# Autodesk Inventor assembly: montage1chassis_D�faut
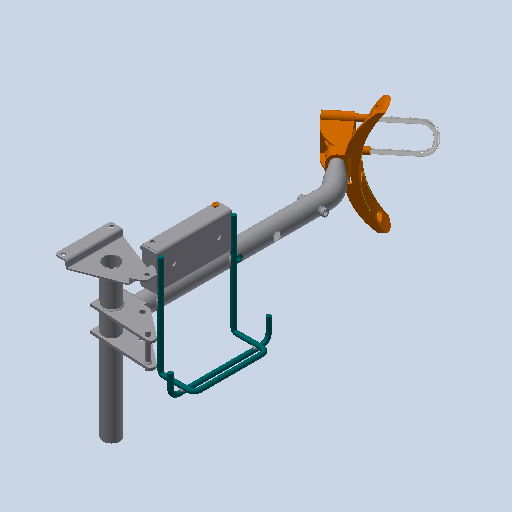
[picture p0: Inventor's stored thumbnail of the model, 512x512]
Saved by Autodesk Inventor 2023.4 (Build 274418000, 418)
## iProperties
Created: 2011-01
Part Number: montage1chassis_D�faut
Document SubType Name: Assembly
Designer: eric
Mass: 436.366 g
Surface Area: 3477.71 cm^2
Volume: 436.366 cm^3
Density: 1 g/cm^3
Author: eric
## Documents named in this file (26)
- C:\Users\bruno\Documents\1-Cours-2024-25\TSsI\7-Dynamique\chariot de golf\chariot_de_golf\chariot_de_golf_trolem\montage1chassis_Defaut.iam
- C:\Users\bruno\Documents\1-Cours-2024-25\TSsI\7-Dynamique\chariot de golf\chariot_de_golf\chariot_de_golf_trolem\bead16_Defaut.ipt
- C:\Users\bruno\Documents\1-Cours-2024-25\TSsI\7-Dynamique\chariot de golf\chariot_de_golf\chariot_de_golf_trolem\1boitier_assemble_Defaut.iam
- C:\Users\bruno\Documents\1-Cours-2024-25\TSsI\7-Dynamique\chariot de golf\chariot_de_golf\chariot_de_golf_trolem\1tube_Defaut.ipt
- C:\Users\bruno\Documents\1-Cours-2024-25\TSsI\7-Dynamique\chariot de golf\chariot_de_golf\chariot_de_golf_trolem\bead7_Defaut.ipt
- C:\Users\bruno\Documents\1-Cours-2024-25\TSsI\7-Dynamique\chariot de golf\chariot_de_golf\chariot_de_golf_trolem\bead3_Defaut.ipt
- C:\Users\bruno\Documents\1-Cours-2024-25\TSsI\7-Dynamique\chariot de golf\chariot_de_golf\chariot_de_golf_trolem\bead15_Defaut.ipt
- C:\Users\bruno\Documents\1-Cours-2024-25\TSsI\7-Dynamique\chariot de golf\chariot_de_golf\chariot_de_golf_trolem\bead4_Defaut.ipt
- C:\Users\bruno\Documents\1-Cours-2024-25\TSsI\7-Dynamique\chariot de golf\chariot_de_golf\chariot_de_golf_trolem\bead18_Defaut.ipt
- C:\Users\bruno\Documents\1-Cours-2024-25\TSsI\7-Dynamique\chariot de golf\chariot_de_golf\chariot_de_golf_trolem\1support_batterie_Defaut.iam
- C:\Users\bruno\Documents\1-Cours-2024-25\TSsI\7-Dynamique\chariot de golf\chariot_de_golf\chariot_de_golf_trolem\1bossage_Defaut.ipt
- C:\Users\bruno\Documents\1-Cours-2024-25\TSsI\7-Dynamique\chariot de golf\chariot_de_golf\chariot_de_golf_trolem\1tube_gauche_Defaut.ipt
- C:\Users\bruno\Documents\1-Cours-2024-25\TSsI\7-Dynamique\chariot de golf\chariot_de_golf\chariot_de_golf_trolem\46Vis CBLZ M5-10.ipt
- C:\Users\bruno\Documents\1-Cours-2024-25\TSsI\7-Dynamique\chariot de golf\chariot_de_golf\chariot_de_golf_trolem\bead8_Defaut.ipt
- C:\Users\bruno\Documents\1-Cours-2024-25\TSsI\7-Dynamique\chariot de golf\chariot_de_golf\chariot_de_golf_trolem\5.1roulement_12x28x8_Defaut.iam
- C:\Users\bruno\Documents\1-Cours-2024-25\TSsI\7-Dynamique\chariot de golf\chariot_de_golf\chariot_de_golf_trolem\41support_bas_Defaut.ipt
- C:\Users\bruno\Documents\1-Cours-2024-25\TSsI\7-Dynamique\chariot de golf\chariot_de_golf\chariot_de_golf_trolem\1bossage2_Defaut.ipt
- C:\Users\bruno\Documents\1-Cours-2024-25\TSsI\7-Dynamique\chariot de golf\chariot_de_golf\chariot_de_golf_trolem\bead14_Defaut.ipt
- C:\Users\bruno\Documents\1-Cours-2024-25\TSsI\7-Dynamique\chariot de golf\chariot_de_golf\chariot_de_golf_trolem\1chape_Defaut.ipt
- C:\Users\bruno\Documents\1-Cours-2024-25\TSsI\7-Dynamique\chariot de golf\chariot_de_golf\chariot_de_golf_trolem\bead5_Defaut.ipt
- C:\Users\bruno\Documents\1-Cours-2024-25\TSsI\7-Dynamique\chariot de golf\chariot_de_golf\chariot_de_golf_trolem\bead17_Defaut.ipt
- C:\Users\bruno\Documents\1-Cours-2024-25\TSsI\7-Dynamique\chariot de golf\chariot_de_golf\chariot_de_golf_trolem\1axe_8mm_Defaut.ipt
- C:\Users\bruno\Documents\1-Cours-2024-25\TSsI\7-Dynamique\chariot de golf\chariot_de_golf\chariot_de_golf_trolem\bead11_Defaut.ipt
- C:\Users\bruno\Documents\1-Cours-2024-25\TSsI\7-Dynamique\chariot de golf\chariot_de_golf\chariot_de_golf_trolem\bead6_Defaut.ipt
- C:\Users\bruno\Documents\1-Cours-2024-25\TSsI\7-Dynamique\chariot de golf\chariot_de_golf\chariot_de_golf_trolem\bead10_Defaut.ipt
- C:\Users\bruno\Documents\1-Cours-2024-25\TSsI\7-Dynamique\chariot de golf\chariot_de_golf\chariot_de_golf_trolem\1fixation_moteur_Defaut.ipt
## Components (28 placed, 25 different names)
1. bead16_Defaut:1
2. 1boitier_assemble_Defaut:1 [sub-assembly]
3. 1tube_Defaut:1
4. bead7_Defaut:1
5. bead3_Defaut:1
6. bead15_Defaut:1
7. bead4_Defaut:1
8. bead18_Defaut:1
9. 1support_batterie_Defaut:1 [sub-assembly]
10. 1bossage_Defaut:1
11. 1tube_gauche_Defaut:1
12. 46Vis CBLZ M5-10:1
13. bead15_Defaut:2
14. bead8_Defaut:1
15. 5.1roulement_12x28x8_Defaut:1 [sub-assembly]
16. 41support_bas_Defaut:1
17. 1bossage2_Defaut:1
18. bead14_Defaut:1
19. 1chape_Defaut:1
20. bead5_Defaut:1
21. bead14_Defaut:2
22. bead17_Defaut:1
23. 1axe_8mm_Defaut:1
24. bead11_Defaut:1
25. bead6_Defaut:1
26. bead10_Defaut:1
27. 1fixation_moteur_Defaut:1
28. 1bossage_Defaut:2
